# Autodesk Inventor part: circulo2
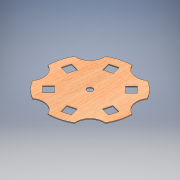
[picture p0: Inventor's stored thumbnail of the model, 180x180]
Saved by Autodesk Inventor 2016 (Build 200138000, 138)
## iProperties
Created: 2016-06
Part Number: circulo2
Material: Genérico
Document SubType Name: Modeling
Designer: adm
Density: 1 g/cm^3
Appearance: Valor por defecto
Author: adm
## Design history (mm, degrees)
sketch "Boceto1"
  geometry: L1 (81.5, 59.5)-(96, 74); L2 (81.5, 59.5)-(60, 81); L3 (96, 74)-(74.5, 95.5); L4 (60, 81)-(74.5, 95.5); L5 (95.045, 116.045)-(95.566, 116.566); L6 (-10.779, 100.331)-(-40.148, 92.462); L7 (-40.148, 92.462)-(-45.455, 112.269); L8 (-10.779, 100.331)-(-16.086, 120.138); L9 (-16.086, 120.138)-(-45.455, 112.269); L10 (-92.279, 40.831)-(-100.148, 11.462); L11 (-100.148, 11.462)-(-119.955, 16.769); L12 (-92.279, 40.831)-(-112.086, 46.138); L13 (-112.086, 46.138)-(-119.955, 16.769); L14 (-81.5, -59.5)-(-60, -81); L15 (-60, -81)-(-74.5, -95.5); L16 (-81.5, -59.5)-(-96, -74); L17 (-96, -74)-(-74.5, -95.5); L18 (10.779, -100.331)-(40.148, -92.462); L19 (40.148, -92.462)-(45.455, -112.269); L20 (10.779, -100.331)-(16.086, -120.138); L21 (16.086, -120.138)-(45.455, -112.269); L22 (92.279, -40.831)-(100.148, -11.462); L23 (100.148, -11.462)-(119.955, -16.769); L24 (92.279, -40.831)-(112.086, -46.138); L25 (112.086, -46.138)-(119.955, -16.769); L26 (-40.148, 92.462)-(-10.779, 100.331); C1 r 10 at (0, 0); A1 r 50 centre (45.655, 170.387) between (0, 150) and (75, 129.904); A2 r 50 centre (-124.732, 124.732) between (-129.904, 75) and (-75, 129.904); A3 r 50 centre (-170.387, -45.655) between (-129.904, -75) and (-150, 0); A4 r 50 centre (-45.655, -170.387) between (0, -150) and (-75, -129.904); A5 r 50 centre (124.732, -124.732) between (129.904, -75) and (75, -129.904); A6 r 50 centre (170.387, 45.655) between (129.904, 75) and (150, 0); A7 r 150 centre (0, 0) between (0, 150) and (-75, 129.904); A8 r 150 centre (0, 0) between (-129.904, 75) and (-150, 0); A9 r 150 centre (0, 0) between (-129.904, -75) and (-75, -129.904); A10 r 150 centre (0, 0) between (0, -150) and (75, -129.904); A11 r 150 centre (0, 0) between (129.904, -75) and (150, 0); A12 r 150 centre (0, 0) between (129.904, 75) and (75, 129.904)
  constraints: 52 end point, 25 point on circle, 13 centre point, 2 equal length, 1 coincident, 74 other
  dimensions: "d4" = 50 radius of A1; "d11" = 360 deg dimension on A7.centre A1.centre (derived); "d15" = 360 deg dimension on A7.centre L1.start (derived); "d17" = 20 diameter of C1
extrude "Extrusión1" new body sketch "Boceto1" distance "d18" = 3; taper "d19" = 0 deg
sketch "Boceto2"
  geometry: L1 (-40.148, 92.462)-(-10.779, 100.331); L2 (-37.56, 82.802)-(-8.19, 90.672); L3 (-10.779, 100.331)-(-8.19, 90.672); L4 (-40.148, 92.462)-(-37.56, 82.802); L5 (-100.148, 11.462)-(-92.279, 40.831); L6 (-100.148, 11.462)-(-90.489, 8.873); L7 (-90.489, 8.873)-(-82.619, 38.243); L8 (-92.279, 40.831)-(-82.619, 38.243); L9 (-60, -81)-(-81.5, -59.5); L10 (-60, -81)-(-52.929, -73.929); L11 (-52.929, -73.929)-(-74.429, -52.429); L12 (-81.5, -59.5)-(-74.429, -52.429); L13 (40.148, -92.462)-(10.779, -100.331); L14 (40.148, -92.462)-(37.56, -82.802); L15 (37.56, -82.802)-(8.19, -90.672); L16 (10.779, -100.331)-(8.19, -90.672); L17 (100.148, -11.462)-(92.279, -40.831); L18 (100.148, -11.462)-(90.489, -8.873); L19 (90.489, -8.873)-(82.619, -38.243); L20 (92.279, -40.831)-(82.619, -38.243); L21 (60, 81)-(81.5, 59.5); L22 (60, 81)-(52.929, 73.929); L23 (52.929, 73.929)-(74.429, 52.429); L24 (81.5, 59.5)-(74.429, 52.429); C1 r 10 at (0, 0) reference; A1 r 150 centre (0, 0) between (129.904, 75) and (75, 129.904) reference; 2 further points
  constraints: 48 end point, 2 parallel, 1 coincident, 49 other
  dimensions: "d23" = 10 distance between parallel lines of L1 L2; "d26" = 360 deg dimension on point (0, 0) L1.start (derived)
extrude "Extrusión2" cut sketch "Boceto2" distance "d28" = 10; taper "d29" = 0 deg
node "Sólido1"
other parameters: "d5" = 14.84924
